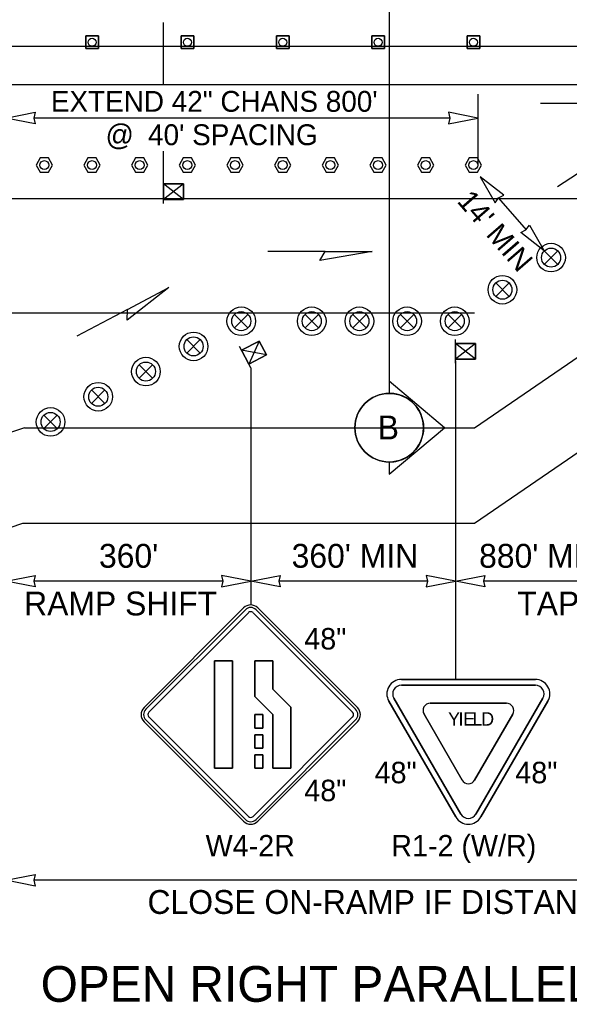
# Model space of a CAD drawing. Extents: x 99999 to 100116, y 99995 to 100013.
# Drawn here: x 100050.649 to 100052.494, y 100004.799 to 100008.096 of the extents above; entities that cross this region are included whole.
import ezdxf

# ---------------------------------------------------------------- set-up
doc = ezdxf.new("R2010")
doc.units = 0
for name, color, linetype in [('RD_MK_LineEdgeYellow', 7, 'Continuous'), ('RD_MK_LineLane', 7, 'Continuous'), ('SH_DE_DetailHeading2Text', 7, 'Continuous'), ('SH_GI_SectionCut', 7, 'Continuous'), ('TR_SN_ConstructionSigns', 7, 'Continuous'), ('TR_WZ_PortableSignMount5ftMinBlk-Org', 7, 'Continuous'), ('TR_WZ_PortableSignMount5ftMinRed-Wht', 7, 'Continuous'), ('TR_WZ_TallChanDevice', 7, 'Continuous'), ('TR_WZ_TrafficCone', 7, 'Continuous'), ('TR_WZ_TrafficSafetyDrum', 7, 'Continuous'), ('TR_WZ_WorkZoneDetails', 7, 'Continuous'), ('TR_WZ_WorkZoneTextCurrent', 7, 'Continuous')]:
    doc.layers.add(name, color=color, linetype=linetype)

msp = doc.modelspace()

# ---------------------------------------------------------------- linework, layer by layer
at = {"layer": 'RD_MK_LineEdgeYellow'}
for p, q in [((100048.195, 100007.8789), (100055.43, 100007.8789)), ((100052.1758, 100006.7269), (100052.7368, 100007.1109)), ((100050.6655, 100006.7269), (100048.195, 100005.8927)), ((100050.6655, 100006.7269), (100052.1758, 100006.7269))]:
    msp.add_line(p, q, dxfattribs=at)
at = {"layer": 'RD_MK_LineLane'}
for points in [[(100055.43, 100007.4949), (100048.195, 100007.4949)], [(100052.1758, 100007.1109), (100050.6024, 100007.1109)], [(100052.1758, 100007.1109), (100050.6024, 100007.1109)]]:
    msp.add_lwpolyline(points, dxfattribs=at)
at = {"layer": 'SH_GI_SectionCut'}
for p, q in [((100051.8894, 100008.3179), (100051.8894, 100006.8828)), ((100051.8894, 100006.8828), (100051.8894, 100006.8421)), ((100052.0755, 100006.7269), (100051.8894, 100006.8828)), ((100051.8894, 100006.571), (100052.0755, 100006.7269)), ((100051.8894, 100006.6117), (100051.8894, 100006.571))]:
    msp.add_line(p, q, dxfattribs=at)
msp.add_circle((100051.8894, 100006.7269), 0.1152, dxfattribs=at)
for start, end in [(0, 269.9978), (269.9978, 90.0022), (269.9978, 0)]:
    msp.add_arc((100051.8894, 100006.7269), 0.1152, start, end, dxfattribs=at)
at = {"layer": 'TR_SN_ConstructionSigns'}
for p, q in [((100051.4008, 100006.122), (100051.0667, 100005.7879)), ((100051.4067, 100006.1161), (100051.0726, 100005.7819)), ((100051.0826, 100005.772), (100051.4167, 100006.1061)), ((100051.4326, 100006.1061), (100051.7667, 100005.772)), ((100051.7766, 100005.7819), (100051.4425, 100006.1161)), ((100051.7826, 100005.7879), (100051.4485, 100006.122)), ((100051.303, 100005.944), (100051.3634, 100005.944)), ((100051.303, 100005.584), (100051.303, 100005.944)), ((100051.3634, 100005.944), (100051.303, 100005.944)), ((100051.303, 100005.944), (100051.303, 100005.584)), ((100051.3634, 100005.944), (100051.3634, 100005.584)), ((100051.3634, 100005.584), (100051.3634, 100005.944)), ((100051.4387, 100005.944), (100051.4992, 100005.944)), ((100051.4387, 100005.8245), (100051.4387, 100005.944)), ((100051.4992, 100005.944), (100051.4387, 100005.944)), ((100051.4387, 100005.944), (100051.4387, 100005.8245)), ((100051.4992, 100005.944), (100051.4992, 100005.8496)), ((100051.4992, 100005.8496), (100051.4992, 100005.944)), ((100052.3799, 100005.8822), (100051.9302, 100005.8822)), ((100051.4992, 100005.8496), (100051.5596, 100005.7891)), ((100051.5596, 100005.7891), (100051.4992, 100005.8496)), ((100051.9302, 100005.8627), (100051.9302, 100005.8629)), ((100051.9302, 100005.8629), (100052.1551, 100005.8629)), ((100052.1551, 100005.8629), (100051.9302, 100005.8629)), ((100051.9302, 100005.8629), (100051.9302, 100005.8627)), ((100051.4992, 100005.764), (100051.4387, 100005.8245)), ((100051.4387, 100005.8245), (100051.4992, 100005.764)), ((100052.1129, 100005.4205), (100051.8881, 100005.8091)), ((100051.8881, 100005.8091), (100052.1129, 100005.4205)), ((100052.1298, 100005.4302), (100051.9049, 100005.8189)), ((100051.9049, 100005.8189), (100052.1298, 100005.4302)), ((100052.4052, 100005.8189), (100052.1804, 100005.4303)), ((100052.1804, 100005.4303), (100052.4052, 100005.8189)), ((100052.422, 100005.8091), (100052.1972, 100005.4205)), ((100052.1972, 100005.4205), (100052.422, 100005.8091)), ((100051.5596, 100005.7891), (100051.5596, 100005.584)), ((100051.5596, 100005.584), (100051.5596, 100005.7891)), ((100052.1551, 100005.802), (100052.0273, 100005.802)), ((100052.0273, 100005.802), (100052.1551, 100005.802)), ((100052.2828, 100005.802), (100052.1551, 100005.802)), ((100052.1551, 100005.802), (100052.2828, 100005.802)), ((100051.0667, 100005.7402), (100051.4008, 100005.4061)), ((100051.0726, 100005.7462), (100051.4067, 100005.412)), ((100051.4167, 100005.422), (100051.0826, 100005.7561)), ((100051.7667, 100005.7561), (100051.4326, 100005.422)), ((100051.4387, 100005.764), (100051.4654, 100005.764)), ((100051.4387, 100005.719), (100051.4387, 100005.764)), ((100051.4654, 100005.764), (100051.4387, 100005.764)), ((100051.4387, 100005.764), (100051.4387, 100005.719)), ((100051.4425, 100005.412), (100051.7766, 100005.7462)), ((100051.4485, 100005.4061), (100051.7826, 100005.7402)), ((100051.4654, 100005.764), (100051.4654, 100005.719)), ((100051.4654, 100005.719), (100051.4654, 100005.764)), ((100051.4992, 100005.584), (100051.4992, 100005.764)), ((100051.4992, 100005.764), (100051.4992, 100005.584)), ((100052.0062, 100005.7654), (100052.134, 100005.5445)), ((100052.134, 100005.5445), (100052.0062, 100005.7654)), ((100052.1761, 100005.5445), (100052.3039, 100005.7654)), ((100052.3039, 100005.7654), (100052.1761, 100005.5445)), ((100051.4654, 100005.719), (100051.4387, 100005.719)), ((100051.4387, 100005.719), (100051.4654, 100005.719)), ((100051.4387, 100005.6965), (100051.4654, 100005.6965)), ((100051.4387, 100005.6515), (100051.4387, 100005.6965)), ((100051.4654, 100005.6965), (100051.4387, 100005.6965)), ((100051.4387, 100005.6965), (100051.4387, 100005.6515)), ((100051.4654, 100005.6965), (100051.4654, 100005.6515)), ((100051.4654, 100005.6515), (100051.4654, 100005.6965)), ((100051.4654, 100005.6515), (100051.4387, 100005.6515)), ((100051.4387, 100005.6515), (100051.4654, 100005.6515)), ((100051.4387, 100005.629), (100051.4654, 100005.629)), ((100051.4387, 100005.584), (100051.4387, 100005.629)), ((100051.4654, 100005.629), (100051.4387, 100005.629)), ((100051.4387, 100005.629), (100051.4387, 100005.584)), ((100051.4654, 100005.629), (100051.4654, 100005.584)), ((100051.4654, 100005.584), (100051.4654, 100005.629)), ((100051.3634, 100005.584), (100051.303, 100005.584)), ((100051.303, 100005.584), (100051.3634, 100005.584)), ((100051.4654, 100005.584), (100051.4387, 100005.584)), ((100051.4387, 100005.584), (100051.4654, 100005.584)), ((100051.5596, 100005.584), (100051.4992, 100005.584)), ((100051.4992, 100005.584), (100051.5596, 100005.584))]:
    msp.add_line(p, q, dxfattribs=at)
for points in [[(100051.9302, 100005.8822), (100052.3799, 100005.8822)], [(100052.1551, 100005.8629), (100052.3799, 100005.8629), (100052.3799, 100005.8627)], [(100052.3799, 100005.8627), (100052.3799, 100005.8629), (100052.1551, 100005.8629)]]:
    msp.add_lwpolyline(points, dxfattribs=at)
for centre, radius, start, end in [((100051.4246, 100006.0982), 0.0338, 45, 135), ((100051.4246, 100006.0982), 0.0253, 45, 135), ((100051.4246, 100006.0982), 0.0113, 45, 135), ((100051.9302, 100005.8335), 0.0487, 90, 210.0517), ((100051.9302, 100005.8335), 0.0487, 90, 210.0517), ((100052.3799, 100005.8335), 0.0487, 329.9522, 90), ((100052.3799, 100005.8335), 0.0487, 329.9522, 90), ((100051.9302, 100005.8335), 0.0292, 90, 210.0517), ((100051.9302, 100005.8335), 0.0292, 90, 210.0517), ((100052.3799, 100005.8335), 0.0292, 329.9522, 90), ((100052.3799, 100005.8335), 0.0292, 329.9522, 90), ((100051.0905, 100005.764), 0.0338, 135, 225), ((100051.0905, 100005.764), 0.0253, 135, 225), ((100051.0905, 100005.764), 0.0113, 135, 225), ((100051.7587, 100005.764), 0.0113, 315, 45), ((100051.7587, 100005.764), 0.0253, 315, 45), ((100051.7587, 100005.764), 0.0338, 315, 45), ((100052.0273, 100005.7776), 0.0244, 90, 210.0513), ((100052.0273, 100005.7776), 0.0244, 90, 210.0513), ((100052.2828, 100005.7776), 0.0244, 329.9514, 90), ((100052.2828, 100005.7776), 0.0244, 329.9514, 90), ((100052.1551, 100005.5567), 0.0244, 210.0519, 329.9525), ((100052.1551, 100005.5567), 0.0244, 210.0519, 329.9525), ((100051.4246, 100005.4299), 0.0253, 225, 315), ((100051.4246, 100005.4299), 0.0113, 225, 315), ((100052.1551, 100005.4449), 0.0487, 210.0518, 329.9516), ((100052.1551, 100005.4449), 0.0487, 210.0518, 329.9516), ((100052.1551, 100005.4449), 0.0292, 210.0518, 329.9516), ((100052.1551, 100005.4449), 0.0292, 210.0518, 329.9516), ((100051.4246, 100005.4299), 0.0338, 225, 315)]:
    msp.add_arc(centre, radius, start, end, dxfattribs=at)
at = {"layer": 'TR_WZ_PortableSignMount5ftMinBlk-Org'}
for p, q in [((100051.132, 100007.4789), (100051.132, 100007.5589)), ((100051.1987, 100007.5449), (100051.132, 100007.4929)), ((100051.1987, 100007.4929), (100051.132, 100007.5449)), ((100051.1654, 100007.5189), (100051.1654, 100007.5189)), ((100051.1655, 100007.519), (100051.1655, 100007.519)), ((100051.4246, 100006.9281), (100051.3873, 100006.9988)), ((100051.4528, 100007.0176), (100051.4181, 100006.9405)), ((100051.4771, 100006.9716), (100051.3938, 100006.9865)), ((100051.4354, 100006.9791), (100051.4354, 100006.9791)), ((100051.4355, 100006.9792), (100051.4355, 100006.9792))]:
    msp.add_line(p, q, dxfattribs=at)
for points in [[(100051.1987, 100007.5449), (100051.1987, 100007.4929), (100051.132, 100007.4929), (100051.132, 100007.5449)], [(100051.132, 100007.4929), (100051.1987, 100007.4929), (100051.1987, 100007.5449), (100051.132, 100007.5449)], [(100051.4528, 100007.0176), (100051.4771, 100006.9716), (100051.4181, 100006.9405), (100051.3938, 100006.9865)], [(100051.4181, 100006.9405), (100051.4771, 100006.9716), (100051.4528, 100007.0176), (100051.3938, 100006.9865)]]:
    msp.add_lwpolyline(points, close=True, dxfattribs=at)
at = {"layer": 'TR_WZ_PortableSignMount5ftMinRed-Wht'}
for p, q in [((100052.1119, 100006.9432), (100052.1119, 100007.0232)), ((100052.1786, 100007.0092), (100052.1119, 100006.9572)), ((100052.1786, 100006.9572), (100052.1119, 100007.0092)), ((100052.1452, 100006.9832), (100052.1452, 100006.9832)), ((100052.1453, 100006.9832), (100052.1453, 100006.9832))]:
    msp.add_line(p, q, dxfattribs=at)
for points in [[(100052.1786, 100007.0092), (100052.1786, 100006.9572), (100052.1119, 100006.9572), (100052.1119, 100007.0092)], [(100052.1119, 100006.9572), (100052.1786, 100006.9572), (100052.1786, 100007.0092), (100052.1119, 100007.0092)]]:
    msp.add_lwpolyline(points, close=True, dxfattribs=at)
at = {"layer": 'TR_WZ_TallChanDevice'}
for points in [[(100050.7459, 100007.6319), (100050.7182, 100007.6319), (100050.7043, 100007.6079), (100050.7182, 100007.5839), (100050.7459, 100007.5839), (100050.7597, 100007.6079)], [(100050.9059, 100007.6319), (100050.8782, 100007.6319), (100050.8643, 100007.6079), (100050.8782, 100007.5839), (100050.9059, 100007.5839), (100050.9197, 100007.6079)], [(100051.0659, 100007.6319), (100051.0382, 100007.6319), (100051.0243, 100007.6079), (100051.0382, 100007.5839), (100051.0659, 100007.5839), (100051.0797, 100007.6079)], [(100051.2259, 100007.6319), (100051.1982, 100007.6319), (100051.1843, 100007.6079), (100051.1982, 100007.5839), (100051.2259, 100007.5839), (100051.2397, 100007.6079)], [(100051.3859, 100007.6319), (100051.3582, 100007.6319), (100051.3443, 100007.6079), (100051.3582, 100007.5839), (100051.3859, 100007.5839), (100051.3997, 100007.6079)], [(100051.5459, 100007.6319), (100051.5182, 100007.6319), (100051.5043, 100007.6079), (100051.5182, 100007.5839), (100051.5459, 100007.5839), (100051.5597, 100007.6079)], [(100051.7059, 100007.6319), (100051.6782, 100007.6319), (100051.6643, 100007.6079), (100051.6782, 100007.5839), (100051.7059, 100007.5839), (100051.7197, 100007.6079)], [(100051.8659, 100007.6319), (100051.8382, 100007.6319), (100051.8243, 100007.6079), (100051.8382, 100007.5839), (100051.8659, 100007.5839), (100051.8797, 100007.6079)], [(100052.0259, 100007.6319), (100051.9982, 100007.6319), (100051.9843, 100007.6079), (100051.9982, 100007.5839), (100052.0259, 100007.5839), (100052.0397, 100007.6079)], [(100052.1859, 100007.6319), (100052.1582, 100007.6319), (100052.1443, 100007.6079), (100052.1582, 100007.5839), (100052.1859, 100007.5839), (100052.1997, 100007.6079)]]:
    msp.add_lwpolyline(points, close=True, dxfattribs=at)
for points in [[(100050.7459, 100007.6319), (100050.7182, 100007.6319), (100050.7043, 100007.6079), (100050.7182, 100007.5839), (100050.7459, 100007.5839), (100050.7597, 100007.6079), (100050.7459, 100007.6319)], [(100050.9059, 100007.6319), (100050.8782, 100007.6319), (100050.8643, 100007.6079), (100050.8782, 100007.5839), (100050.9059, 100007.5839), (100050.9197, 100007.6079), (100050.9059, 100007.6319)], [(100051.0659, 100007.6319), (100051.0382, 100007.6319), (100051.0243, 100007.6079), (100051.0382, 100007.5839), (100051.0659, 100007.5839), (100051.0797, 100007.6079), (100051.0659, 100007.6319)], [(100051.2259, 100007.6319), (100051.1982, 100007.6319), (100051.1843, 100007.6079), (100051.1982, 100007.5839), (100051.2259, 100007.5839), (100051.2397, 100007.6079), (100051.2259, 100007.6319)], [(100051.3859, 100007.6319), (100051.3582, 100007.6319), (100051.3443, 100007.6079), (100051.3582, 100007.5839), (100051.3859, 100007.5839), (100051.3997, 100007.6079), (100051.3859, 100007.6319)], [(100051.5459, 100007.6319), (100051.5182, 100007.6319), (100051.5043, 100007.6079), (100051.5182, 100007.5839), (100051.5459, 100007.5839), (100051.5597, 100007.6079), (100051.5459, 100007.6319)], [(100051.7059, 100007.6319), (100051.6782, 100007.6319), (100051.6643, 100007.6079), (100051.6782, 100007.5839), (100051.7059, 100007.5839), (100051.7197, 100007.6079), (100051.7059, 100007.6319)], [(100051.8659, 100007.6319), (100051.8382, 100007.6319), (100051.8243, 100007.6079), (100051.8382, 100007.5839), (100051.8659, 100007.5839), (100051.8797, 100007.6079), (100051.8659, 100007.6319)], [(100052.0259, 100007.6319), (100051.9982, 100007.6319), (100051.9843, 100007.6079), (100051.9982, 100007.5839), (100052.0259, 100007.5839), (100052.0397, 100007.6079), (100052.0259, 100007.6319)], [(100052.1859, 100007.6319), (100052.1582, 100007.6319), (100052.1443, 100007.6079), (100052.1582, 100007.5839), (100052.1859, 100007.5839), (100052.1997, 100007.6079), (100052.1859, 100007.6319)]]:
    msp.add_lwpolyline(points, dxfattribs=at)
for centre in [(100050.732, 100007.6079), (100050.892, 100007.6079), (100051.052, 100007.6079), (100051.212, 100007.6079), (100051.372, 100007.6079), (100051.532, 100007.6079), (100051.692, 100007.6079), (100051.852, 100007.6079), (100052.012, 100007.6079), (100052.172, 100007.6079)]:
    msp.add_circle(centre, 0.015, dxfattribs=at)
at = {"layer": 'TR_WZ_TrafficCone'}
for points in [[(100050.8707, 100008.0416), (100050.9134, 100008.0416), (100050.9134, 100007.9989), (100050.8707, 100007.9989), (100050.8707, 100008.0416)], [(100050.8707, 100007.9989), (100050.9134, 100007.9989), (100050.9134, 100008.0416), (100050.8707, 100008.0416), (100050.8707, 100007.9989)], [(100051.1907, 100008.0416), (100051.2334, 100008.0416), (100051.2334, 100007.9989), (100051.1907, 100007.9989), (100051.1907, 100008.0416)], [(100051.1907, 100007.9989), (100051.2334, 100007.9989), (100051.2334, 100008.0416), (100051.1907, 100008.0416), (100051.1907, 100007.9989)], [(100051.5107, 100008.0416), (100051.5534, 100008.0416), (100051.5534, 100007.9989), (100051.5107, 100007.9989), (100051.5107, 100008.0416)], [(100051.5107, 100007.9989), (100051.5534, 100007.9989), (100051.5534, 100008.0416), (100051.5107, 100008.0416), (100051.5107, 100007.9989)], [(100051.8307, 100008.0416), (100051.8734, 100008.0416), (100051.8734, 100007.9989), (100051.8307, 100007.9989), (100051.8307, 100008.0416)], [(100051.8307, 100007.9989), (100051.8734, 100007.9989), (100051.8734, 100008.0416), (100051.8307, 100008.0416), (100051.8307, 100007.9989)], [(100052.1507, 100008.0416), (100052.1934, 100008.0416), (100052.1934, 100007.9989), (100052.1507, 100007.9989), (100052.1507, 100008.0416)], [(100052.1507, 100007.9989), (100052.1934, 100007.9989), (100052.1934, 100008.0416), (100052.1507, 100008.0416), (100052.1507, 100007.9989)]]:
    msp.add_lwpolyline(points, dxfattribs=at)
for centre in [(100050.892, 100008.0202), (100051.212, 100008.0202), (100051.532, 100008.0202), (100051.852, 100008.0202), (100052.172, 100008.0202)]:
    msp.add_circle(centre, 0.0133, dxfattribs=at)
at = {"layer": 'TR_WZ_TrafficSafetyDrum'}
for p, q in [((100052.41, 100007.3201), (100052.4553, 100007.2749)), ((100052.4553, 100007.3201), (100052.41, 100007.2749)), ((100052.2468, 100007.2124), (100052.292, 100007.1672)), ((100052.292, 100007.2124), (100052.2468, 100007.1672)), ((100051.37, 100007.1069), (100051.4153, 100007.0616)), ((100051.4153, 100007.1069), (100051.37, 100007.0616)), ((100051.6068, 100007.1069), (100051.652, 100007.0616)), ((100051.652, 100007.1069), (100051.6068, 100007.0616)), ((100051.7668, 100007.1069), (100051.812, 100007.0616)), ((100051.812, 100007.1069), (100051.7668, 100007.0616)), ((100051.9268, 100007.1069), (100051.972, 100007.0616)), ((100051.972, 100007.1069), (100051.9268, 100007.0616)), ((100052.0868, 100007.1069), (100052.132, 100007.0616)), ((100052.132, 100007.1069), (100052.0868, 100007.0616)), ((100051.21, 100007.0224), (100051.2553, 100006.9771)), ((100051.2553, 100007.0224), (100051.21, 100006.9771)), ((100051.05, 100006.9379), (100051.0953, 100006.8926)), ((100051.0953, 100006.9379), (100051.05, 100006.8926)), ((100050.89, 100006.8534), (100050.9353, 100006.8081)), ((100050.9353, 100006.8534), (100050.89, 100006.8081)), ((100050.73, 100006.7689), (100050.7753, 100006.7236)), ((100050.7753, 100006.7689), (100050.73, 100006.7236))]:
    msp.add_line(p, q, dxfattribs=at)
for centre, radius in [((100052.4327, 100007.2975), 0.048), ((100052.4327, 100007.2975), 0.048), ((100052.4327, 100007.2975), 0.032), ((100052.2694, 100007.1898), 0.048), ((100052.2694, 100007.1898), 0.048), ((100052.2694, 100007.1898), 0.032), ((100051.3927, 100007.0842), 0.048), ((100051.3927, 100007.0842), 0.048), ((100051.6294, 100007.0842), 0.048), ((100051.6294, 100007.0842), 0.048), ((100051.7894, 100007.0842), 0.048), ((100051.7894, 100007.0842), 0.048), ((100051.9494, 100007.0842), 0.048), ((100051.9494, 100007.0842), 0.048), ((100052.1094, 100007.0842), 0.048), ((100052.1094, 100007.0842), 0.048), ((100051.3927, 100007.0842), 0.032), ((100051.6294, 100007.0842), 0.032), ((100051.7894, 100007.0842), 0.032), ((100051.9494, 100007.0842), 0.032), ((100052.1094, 100007.0842), 0.032), ((100051.2327, 100006.9997), 0.048), ((100051.2327, 100006.9997), 0.048), ((100051.2327, 100006.9997), 0.032), ((100051.0727, 100006.9152), 0.048), ((100051.0727, 100006.9152), 0.048), ((100051.0727, 100006.9152), 0.032), ((100050.9127, 100006.8307), 0.048), ((100050.9127, 100006.8307), 0.048), ((100050.9127, 100006.8307), 0.032), ((100050.7527, 100006.7462), 0.048), ((100050.7527, 100006.7462), 0.048), ((100050.7527, 100006.7462), 0.032)]:
    msp.add_circle(centre, radius, dxfattribs=at)
at = {"layer": 'TR_WZ_WorkZoneDetails'}
for p, q in [((100051.132, 100007.8789), (100051.132, 100008.0869)), ((100048.195, 100008.0069), (100055.43, 100008.0069)), ((100052.1871, 100007.8459), (100052.1871, 100007.6079)), ((100052.5898, 100007.8149), (100052.3969, 100007.8149)), ((100052.0933, 100007.7659), (100050.6962, 100007.7659)), ((100051.132, 100007.5589), (100051.132, 100007.6549)), ((100052.6158, 100007.6408), (100052.4548, 100007.5346)), ((100052.2561, 100007.4975), (100052.3486, 100007.391)), ((100051.6748, 100007.3183), (100051.4819, 100007.3183)), ((100051.0112, 100007.1238), (100050.8406, 100007.0337)), ((100051.4246, 100006.9281), (100051.4246, 100006.1319)), ((100052.1119, 100006.9512), (100052.1119, 100005.8822)), ((100052.1758, 100006.4069), (100052.7368, 100006.7909)), ((100048.195, 100005.5689), (100050.6601, 100006.4069)), ((100050.6601, 100006.4069), (100052.1758, 100006.4069)), ((100050.6601, 100006.4069), (100052.1758, 100006.4069)), ((100051.3309, 100006.2119), (100050.6962, 100006.2119)), ((100052.0181, 100006.2119), (100051.5184, 100006.2119)), ((100052.7917, 100006.2119), (100052.2056, 100006.2119)), ((100054.3691, 100005.2082), (100050.6962, 100005.2082))]:
    msp.add_line(p, q, dxfattribs=at)
for points in [[(100050.6024, 100007.7659), (100050.7007, 100007.7851), (100050.6962, 100007.7659), (100050.7007, 100007.7466)], [(100052.1871, 100007.7659), (100052.0888, 100007.7851), (100052.0933, 100007.7659), (100052.0888, 100007.7466)], [(100052.1947, 100007.5683), (100052.2448, 100007.4816), (100052.2563, 100007.4977), (100052.2738, 100007.5069)], [(100052.41, 100007.3201), (100052.3309, 100007.3815), (100052.3484, 100007.3908), (100052.3599, 100007.4069)], [(100051.8321, 100007.3183), (100051.657, 100007.2875), (100051.6748, 100007.3183)], [(100051.1502, 100007.1972), (100051.0098, 100007.0882), (100051.0112, 100007.1238)], [(100050.6024, 100006.2119), (100050.7007, 100006.2312), (100050.6962, 100006.2119), (100050.7007, 100006.1926)], [(100051.4246, 100006.2119), (100051.3263, 100006.2312), (100051.3309, 100006.2119), (100051.3263, 100006.1926)], [(100051.4246, 100006.2119), (100051.5229, 100006.2312), (100051.5184, 100006.2119), (100051.5229, 100006.1926)], [(100052.1119, 100006.2119), (100052.0136, 100006.2312), (100052.0181, 100006.2119), (100052.0136, 100006.1926)], [(100052.1119, 100006.2119), (100052.2102, 100006.2312), (100052.2056, 100006.2119), (100052.2102, 100006.1926)], [(100050.6024, 100005.2082), (100050.7007, 100005.2275), (100050.6962, 100005.2082), (100050.7007, 100005.1889)]]:
    msp.add_lwpolyline(points, close=True, dxfattribs=at)

# ---------------------------------------------------------------- texts
at = {"layer": 'SH_DE_DetailHeading2Text'}
msp.add_text('OPEN RIGHT PARALLEL ON-RAMP DETAIL', height=0.12, rotation=360, dxfattribs=at).set_placement((100050.7196, 100004.8003))
at = {"layer": 'SH_GI_SectionCut'}
msp.add_text('B', height=0.08, rotation=359.99, dxfattribs=at).set_placement((100051.8507, 100006.6876))
at = {"layer": 'TR_SN_ConstructionSigns'}
for s, p in [('48"', (100051.6044, 100005.9826)), ('48"', (100052.3128, 100005.5337)), ('48"', (100051.6044, 100005.4735)), ('W4-2R', (100051.2732, 100005.2882)), ('R1-2 (W/R)', (100051.8963, 100005.2882))]:
    msp.add_text(s, height=0.072, rotation=360, dxfattribs=at).set_placement(p)
for s, height, p in [('Y', 0.045, (100052.0869, 100005.7271)), ('I', 0.045, (100052.122, 100005.7271)), ('E', 0.045, (100052.1382, 100005.7271)), ('L', 0.045, (100052.1688, 100005.7271)), ('D', 0.045, (100052.198, 100005.7271)), ('48"', 0.072, (100051.8404, 100005.5337))]:
    msp.add_text(s, height=height, dxfattribs=at).set_placement(p)
at = {"layer": 'TR_WZ_WorkZoneTextCurrent'}
for s, height, p in [('EXTEND 42" CHANS 800\'', 0.07, (100050.7538, 100007.7869)), ('@', 0.07, (100050.9373, 100007.6749)), ("40' SPACING", 0.07, (100051.08, 100007.6749)), ("360'", 0.08, (100050.9153, 100006.2569)), ("360' MIN", 0.08, (100051.5618, 100006.2569)), ("880' MERGE", 0.08, (100052.1911, 100006.2569)), ('RAMP SHIFT', 0.08, (100050.6641, 100006.0969)), ('TAPER', 0.08, (100052.3192, 100006.0969)), ('CLOSE ON-RAMP IF DISTANCE IS NOT AVAILABLE', 0.08, (100051.0782, 100005.0953))]:
    msp.add_text(s, height=height, dxfattribs=at).set_placement(p)
msp.add_text("14' MIN", height=0.07, rotation=310.9418, dxfattribs=at).set_placement((100052.1143, 100007.4853))

doc.saveas('drawing.dxf')
